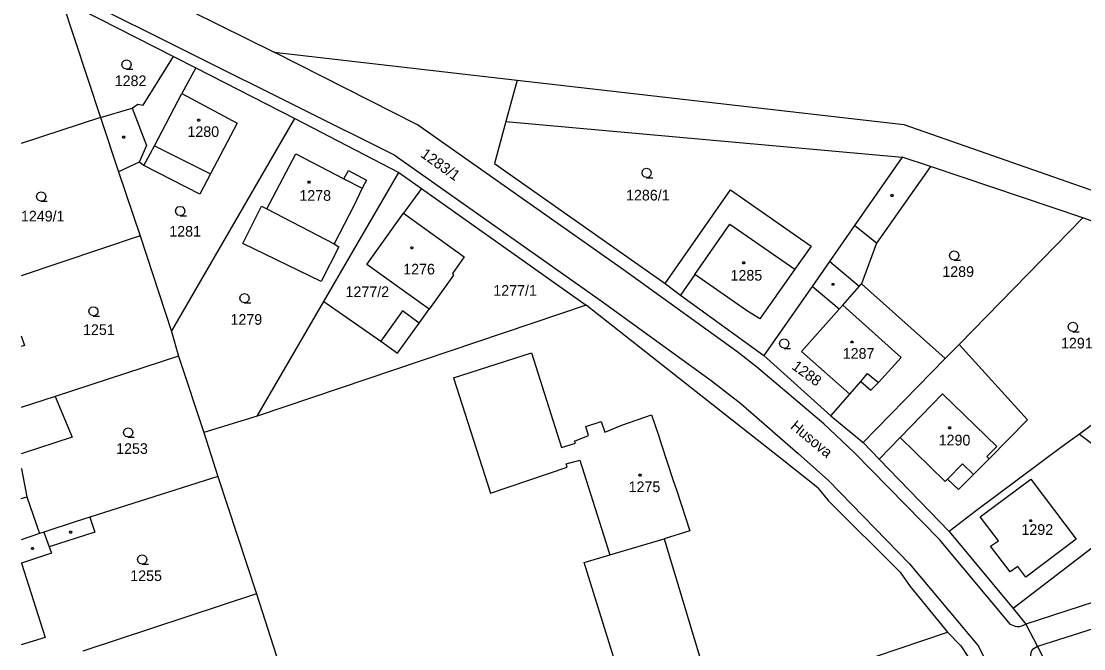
# Model space of a CAD drawing. Extents: x -621797 to -620972, y -1175539 to -1174697.
# Drawn here: x -621790.3 to -621620.7, y -1175230.7 to -1175130.5 of the extents above; entities that cross this region are included whole.
import ezdxf

# ---------------------------------------------------------------- set-up
doc = ezdxf.new("R2010")
doc.units = 0
for name, color, linetype in [('INZ mimo EON - nadz', 7, 'Continuous'), ('Rozvod plynu EON', 7, 'Continuous'), ('SDEL EON', 7, 'Continuous'), ('SDEL EON - popis', 7, 'Continuous'), ('Silnoproud EON', 7, 'Continuous'), ('Silnoproud EON - popis', 7, 'Continuous')]:
    doc.layers.add(name, color=color, linetype=linetype)

msp = doc.modelspace()

# ---------------------------------------------------------------- linework, layer by layer
at = {"layer": 'Rozvod plynu EON'}
for points in [[(-621761.88, -1175146.19), (-621761.79, -1175146.34), (-621761.88, -1175146.49), (-621762.06, -1175146.49), (-621762.15, -1175146.34), (-621762.06, -1175146.19)], [(-621773.89, -1175148.88), (-621773.8, -1175149.03), (-621773.89, -1175149.18), (-621774.07, -1175149.18), (-621774.16, -1175149.03), (-621774.07, -1175148.88)], [(-621744.28, -1175156.07), (-621744.19, -1175156.22), (-621744.28, -1175156.37), (-621744.46, -1175156.37), (-621744.55, -1175156.22), (-621744.46, -1175156.07)], [(-621651.23, -1175158.19), (-621651.14, -1175158.34), (-621651.23, -1175158.49), (-621651.41, -1175158.49), (-621651.5, -1175158.34), (-621651.41, -1175158.19)], [(-621727.87, -1175166.57), (-621727.78, -1175166.72), (-621727.87, -1175166.87), (-621728.05, -1175166.87), (-621728.14, -1175166.72), (-621728.05, -1175166.57)], [(-621674.89, -1175168.95), (-621674.8, -1175169.1), (-621674.89, -1175169.25), (-621675.07, -1175169.25), (-621675.16, -1175169.1), (-621675.07, -1175168.95)], [(-621660.62, -1175172.38), (-621660.53, -1175172.53), (-621660.62, -1175172.68), (-621660.8, -1175172.68), (-621660.89, -1175172.53), (-621660.8, -1175172.38)], [(-621657.59, -1175181.58), (-621657.5, -1175181.73), (-621657.59, -1175181.88), (-621657.77, -1175181.88), (-621657.86, -1175181.73), (-621657.77, -1175181.58)], [(-621642, -1175195.29), (-621641.91, -1175195.44), (-621642, -1175195.59), (-621642.18, -1175195.59), (-621642.27, -1175195.44), (-621642.18, -1175195.29)], [(-621691.46, -1175202.86), (-621691.37, -1175203.01), (-621691.46, -1175203.16), (-621691.64, -1175203.16), (-621691.73, -1175203.01), (-621691.64, -1175202.86)], [(-621629.07, -1175210.1), (-621628.98, -1175210.25), (-621629.07, -1175210.4), (-621629.25, -1175210.4), (-621629.34, -1175210.25), (-621629.25, -1175210.1)], [(-621782.35, -1175211.94), (-621782.26, -1175212.09), (-621782.35, -1175212.24), (-621782.53, -1175212.24), (-621782.62, -1175212.09), (-621782.53, -1175211.94)], [(-621788.42, -1175214.55), (-621788.33, -1175214.7), (-621788.42, -1175214.85), (-621788.6, -1175214.85), (-621788.69, -1175214.7), (-621788.6, -1175214.55)]]:
    msp.add_lwpolyline(points, close=True, dxfattribs=at)
at = {"layer": 'SDEL EON'}
for points in [[(-621773.48, -1175138.19), (-621773.86, -1175138.09), (-621774.13, -1175137.82), (-621774.23, -1175137.45), (-621774.13, -1175137.08), (-621773.86, -1175136.81), (-621773.49, -1175136.71), (-621773.12, -1175136.81), (-621772.85, -1175137.08), (-621772.75, -1175137.46), (-621772.85, -1175137.84), (-621773.12, -1175138.11), (-621773.5, -1175138.21), (-621772.5, -1175138.21)], [(-621690.46, -1175155.49), (-621690.84, -1175155.39), (-621691.11, -1175155.12), (-621691.21, -1175154.75), (-621691.11, -1175154.38), (-621690.84, -1175154.11), (-621690.47, -1175154.01), (-621690.1, -1175154.11), (-621689.83, -1175154.38), (-621689.73, -1175154.76), (-621689.83, -1175155.14), (-621690.1, -1175155.41), (-621690.48, -1175155.51), (-621689.48, -1175155.51)], [(-621787.14, -1175159.26), (-621787.52, -1175159.16), (-621787.79, -1175158.89), (-621787.89, -1175158.52), (-621787.79, -1175158.15), (-621787.52, -1175157.88), (-621787.15, -1175157.78), (-621786.78, -1175157.88), (-621786.51, -1175158.15), (-621786.41, -1175158.53), (-621786.51, -1175158.91), (-621786.78, -1175159.18), (-621787.16, -1175159.28), (-621786.16, -1175159.28)], [(-621764.93, -1175161.57), (-621765.31, -1175161.47), (-621765.58, -1175161.2), (-621765.68, -1175160.83), (-621765.58, -1175160.46), (-621765.31, -1175160.19), (-621764.94, -1175160.09), (-621764.57, -1175160.19), (-621764.3, -1175160.46), (-621764.2, -1175160.84), (-621764.3, -1175161.22), (-621764.57, -1175161.49), (-621764.95, -1175161.59), (-621763.95, -1175161.59)], [(-621641.36, -1175168.65), (-621641.74, -1175168.55), (-621642.01, -1175168.28), (-621642.11, -1175167.91), (-621642.01, -1175167.54), (-621641.74, -1175167.27), (-621641.37, -1175167.17), (-621641, -1175167.27), (-621640.73, -1175167.54), (-621640.63, -1175167.92), (-621640.73, -1175168.3), (-621641, -1175168.57), (-621641.38, -1175168.67), (-621640.38, -1175168.67)], [(-621754.66, -1175175.47), (-621755.04, -1175175.37), (-621755.31, -1175175.1), (-621755.41, -1175174.73), (-621755.31, -1175174.36), (-621755.04, -1175174.09), (-621754.67, -1175173.99), (-621754.3, -1175174.09), (-621754.03, -1175174.36), (-621753.93, -1175174.74), (-621754.03, -1175175.12), (-621754.3, -1175175.39), (-621754.68, -1175175.49), (-621753.68, -1175175.49)], [(-621778.79, -1175177.58), (-621779.17, -1175177.48), (-621779.44, -1175177.21), (-621779.54, -1175176.84), (-621779.44, -1175176.47), (-621779.17, -1175176.2), (-621778.8, -1175176.1), (-621778.43, -1175176.2), (-621778.16, -1175176.47), (-621778.06, -1175176.85), (-621778.16, -1175177.23), (-621778.43, -1175177.5), (-621778.81, -1175177.6), (-621777.81, -1175177.6)], [(-621622.41, -1175180.07), (-621622.79, -1175179.97), (-621623.06, -1175179.7), (-621623.16, -1175179.33), (-621623.06, -1175178.96), (-621622.79, -1175178.69), (-621622.42, -1175178.59), (-621622.05, -1175178.69), (-621621.78, -1175178.96), (-621621.68, -1175179.34), (-621621.78, -1175179.72), (-621622.05, -1175179.99), (-621622.43, -1175180.09), (-621621.43, -1175180.09)], [(-621668.5, -1175182.73), (-621668.88, -1175182.63), (-621669.15, -1175182.36), (-621669.25, -1175181.99), (-621669.15, -1175181.62), (-621668.88, -1175181.35), (-621668.51, -1175181.25), (-621668.14, -1175181.35), (-621667.87, -1175181.62), (-621667.77, -1175182), (-621667.87, -1175182.38), (-621668.14, -1175182.65), (-621668.52, -1175182.75), (-621667.52, -1175182.75)], [(-621773.25, -1175196.9), (-621773.63, -1175196.8), (-621773.9, -1175196.53), (-621774, -1175196.16), (-621773.9, -1175195.79), (-621773.63, -1175195.52), (-621773.26, -1175195.42), (-621772.89, -1175195.52), (-621772.62, -1175195.79), (-621772.52, -1175196.17), (-621772.62, -1175196.55), (-621772.89, -1175196.82), (-621773.27, -1175196.92), (-621772.27, -1175196.92)], [(-621771, -1175217.19), (-621771.38, -1175217.09), (-621771.65, -1175216.82), (-621771.75, -1175216.45), (-621771.65, -1175216.08), (-621771.38, -1175215.81), (-621771.01, -1175215.71), (-621770.64, -1175215.81), (-621770.37, -1175216.08), (-621770.27, -1175216.46), (-621770.37, -1175216.84), (-621770.64, -1175217.11), (-621771.02, -1175217.21), (-621770.02, -1175217.21)]]:
    msp.add_lwpolyline(points, dxfattribs=at)
at = {"layer": 'SDEL EON - popis'}
for p, q in [((-621783.22, -1175125.7), (-621745.71, -1175144.4)), ((-621727.07, -1175147.1), (-621749.91, -1175135.5)), ((-621769.06, -1175150.42), (-621764.69, -1175142.05)), ((-621772.58, -1175144.39), (-621770.3, -1175150.4)), ((-621745.71, -1175144.4), (-621730.8, -1175151.89)), ((-621694.18, -1175170.2), (-621727.07, -1175147.1)), ((-621770.3, -1175150.4), (-621771.49, -1175153.02)), ((-621770.72, -1175153.59), (-621769.06, -1175150.42)), ((-621769.06, -1175150.42), (-621760.1, -1175154.91)), ((-621730.8, -1175151.89), (-621697.74, -1175175.18)), ((-621738.82, -1175155.67), (-621735.86, -1175157.2)), ((-621751.1, -1175160.49), (-621740.33, -1175166.09)), ((-621682.8, -1175170.94), (-621677.18, -1175162.92)), ((-621677.18, -1175162.92), (-621666.81, -1175170.1)), ((-621653.77, -1175165.95), (-621657.29, -1175163.16)), ((-621656.54, -1175172.89), (-621661.29, -1175168.88)), ((-621676.09, -1175183.28), (-621694.18, -1175170.2)), ((-621659.16, -1175175.85), (-621656.54, -1175172.89)), ((-621656.54, -1175172.89), (-621656.18, -1175172.48)), ((-621697.74, -1175175.18), (-621680.17, -1175187.88)), ((-621659.73, -1175176.51), (-621659.16, -1175175.85)), ((-621649.83, -1175184.21), (-621659.16, -1175175.85)), ((-621729.46, -1175176.79), (-621732.9, -1175181.59)), ((-621726.78, -1175178.71), (-621729.46, -1175176.79)), ((-621672.93, -1175185.68), (-621676.09, -1175183.28)), ((-621721.33, -1175187.46), (-621708.86, -1175183.49)), ((-621708.86, -1175183.49), (-621704.06, -1175198.6)), ((-621653.46, -1175188.18), (-621649.83, -1175184.21)), ((-621662.16, -1175194.79), (-621672.93, -1175185.68)), ((-621721.33, -1175187.46), (-621715.42, -1175205.85)), ((-621680.17, -1175187.88), (-621675.41, -1175191.56)), ((-621658.05, -1175190.04), (-621656.29, -1175188.04)), ((-621656.29, -1175188.04), (-621655.19, -1175186.78)), ((-621656.29, -1175188.04), (-621654.66, -1175189.43)), ((-621655.19, -1175186.78), (-621653.46, -1175188.18)), ((-621654.66, -1175189.43), (-621653.46, -1175188.18)), ((-621643.22, -1175190), (-621650.01, -1175196.99)), ((-621634.59, -1175198.43), (-621643.22, -1175190)), ((-621675.41, -1175191.56), (-621666.27, -1175199.53)), ((-621694.41, -1175195.03), (-621689.67, -1175193.36)), ((-621689.67, -1175193.36), (-621688.6, -1175196.59)), ((-621700.19, -1175195.24), (-621697.71, -1175194.45)), ((-621697.71, -1175194.45), (-621697.15, -1175196.13)), ((-621697.15, -1175196.13), (-621694.41, -1175195.03)), ((-621657.34, -1175199.35), (-621662.16, -1175194.79)), ((-621701.98, -1175197.57), (-621699.73, -1175196.67)), ((-621699.73, -1175196.67), (-621700.19, -1175195.24)), ((-621688.6, -1175196.59), (-621688.13, -1175198.01)), ((-621704.06, -1175198.6), (-621701.85, -1175197.9)), ((-621701.85, -1175197.9), (-621701.98, -1175197.57)), ((-621688.13, -1175198.01), (-621686.21, -1175203.85)), ((-621636.17, -1175200), (-621634.59, -1175198.43)), ((-621666.27, -1175199.53), (-621661.43, -1175203.85)), ((-621643.73, -1175213.24), (-621657.34, -1175199.35)), ((-621635.81, -1175200.37), (-621636.17, -1175200)), ((-621715.42, -1175205.85), (-621703.14, -1175201.7)), ((-621703.31, -1175201.21), (-621701.12, -1175200.58)), ((-621703.14, -1175201.7), (-621703.31, -1175201.21)), ((-621701.12, -1175200.58), (-621696.98, -1175213.69)), ((-621642.44, -1175203.65), (-621640.04, -1175201.2)), ((-621640.04, -1175201.2), (-621638.28, -1175202.87)), ((-621790.31, -1175202.007), (-621790.29, -1175202)), ((-621637.21, -1175209.62), (-621629.13, -1175203.63)), ((-621629.13, -1175203.63), (-621621.89, -1175213.2)), ((-621686.21, -1175203.85), (-621685.72, -1175205.32)), ((-621685.72, -1175205.32), (-621683.56, -1175211.87)), ((-621661.43, -1175203.85), (-621648.53, -1175217.13)), ((-621790.31, -1175206.732), (-621789.44, -1175206.45)), ((-621634.32, -1175213.46), (-621637.21, -1175209.62)), ((-621786.69, -1175212.09), (-621785.86, -1175214.41)), ((-621683.56, -1175211.87), (-621687.68, -1175213.14)), ((-621696.98, -1175213.69), (-621696.54, -1175215.07)), ((-621696.34, -1175215.72), (-621687.68, -1175213.14)), ((-621687.68, -1175213.14), (-621681.17, -1175234.78)), ((-621632.38, -1175226.81), (-621643.73, -1175213.24)), ((-621635.56, -1175214.34), (-621634.32, -1175213.46)), ((-621621.89, -1175213.2), (-621629.95, -1175219.26)), ((-621696.54, -1175215.07), (-621696.34, -1175215.72)), ((-621632.44, -1175218.44), (-621635.56, -1175214.34)), ((-621790.31, -1175216.989), (-621790.29, -1175217.05)), ((-621700.46, -1175216.95), (-621696.34, -1175215.72)), ((-621693.77, -1175238.42), (-621700.46, -1175216.95)), ((-621648.53, -1175217.13), (-621637.47, -1175230.28)), ((-621631.22, -1175217.57), (-621632.44, -1175218.44)), ((-621629.95, -1175219.26), (-621631.22, -1175217.57)), ((-621637.47, -1175230.28), (-621625.14, -1175255.82))]:
    msp.add_line(p, q, dxfattribs=at)
for points in [[(-621629.91, -1175226.79), (-621631.34, -1175227.2), (-621632.38, -1175226.81)], [(-621628.06, -1175230.33), (-621629.04, -1175231.05), (-621629.18, -1175232.45)]]:
    msp.add_spline(points, degree=3, dxfattribs=at)
at = {"layer": 'Silnoproud EON'}
for p, q in [((-621774.82, -1175123.16), (-621749.91, -1175135.5)), ((-621783.91, -1175127), (-621777.64, -1175145.9)), ((-621783.91, -1175127), (-621766.01, -1175136.16)), ((-621749.91, -1175135.5), (-621711.12, -1175139.94)), ((-621770.84, -1175143.91), (-621766.01, -1175136.16)), ((-621766.01, -1175136.16), (-621762.45, -1175137.98)), ((-621762.45, -1175137.98), (-621764.69, -1175142.05)), ((-621762.45, -1175137.98), (-621746.62, -1175146.06)), ((-621711.12, -1175139.94), (-621712.93, -1175146.52)), ((-621711.12, -1175139.94), (-621649.41, -1175147.01)), ((-621764.69, -1175142.05), (-621755.84, -1175146.81)), ((-621772.58, -1175144.39), (-621771.71, -1175143.77)), ((-621771.71, -1175143.77), (-621770.84, -1175143.91)), ((-621777.64, -1175145.9), (-621790.31, -1175150.045)), ((-621777.64, -1175145.9), (-621772.58, -1175144.39)), ((-621777.64, -1175145.9), (-621774.76, -1175154.58)), ((-621766.31, -1175180.08), (-621746.62, -1175146.06)), ((-621755.84, -1175146.81), (-621760.1, -1175154.91)), ((-621746.62, -1175146.06), (-621730.05, -1175154.67)), ((-621712.93, -1175146.52), (-621714.78, -1175153.26)), ((-621712.93, -1175146.52), (-621649.66, -1175152.23)), ((-621649.41, -1175147.01), (-621602.94, -1175163.25)), ((-621751.1, -1175160.49), (-621746.47, -1175151.7)), ((-621746.47, -1175151.7), (-621738.82, -1175155.67)), ((-621649.66, -1175152.23), (-621657.29, -1175163.16)), ((-621645.15, -1175153.74), (-621649.66, -1175152.23)), ((-621771.49, -1175153.02), (-621774.76, -1175154.58)), ((-621770.72, -1175153.59), (-621771.49, -1175153.02)), ((-621761.79, -1175158.15), (-621770.72, -1175153.59)), ((-621738.82, -1175155.67), (-621738.08, -1175154.34)), ((-621738.08, -1175154.34), (-621735.18, -1175155.92)), ((-621714.78, -1175153.26), (-621687.53, -1175172.38)), ((-621645.15, -1175153.74), (-621653.77, -1175165.95)), ((-621620.81, -1175161.91), (-621645.15, -1175153.74)), ((-621774.76, -1175154.58), (-621771.35, -1175164.81)), ((-621760.1, -1175154.91), (-621761.79, -1175158.15)), ((-621742.02, -1175175.28), (-621730.05, -1175154.67)), ((-621735.18, -1175155.92), (-621735.86, -1175157.2)), ((-621730.05, -1175154.67), (-621726.42, -1175157.24)), ((-621735.86, -1175157.2), (-621737.14, -1175159.9)), ((-621726.42, -1175157.24), (-621729.27, -1175161.19)), ((-621726.42, -1175157.24), (-621700.14, -1175175.85)), ((-621687.53, -1175172.38), (-621677.09, -1175157.44)), ((-621677.09, -1175157.44), (-621664.22, -1175166.43)), ((-621754.96, -1175165.99), (-621751.98, -1175160.06)), ((-621751.98, -1175160.06), (-621751.1, -1175160.49)), ((-621737.14, -1175159.9), (-621740.33, -1175166.09)), ((-621735.16, -1175169.36), (-621729.27, -1175161.19)), ((-621729.27, -1175161.19), (-621719.61, -1175168.17)), ((-621620.81, -1175161.91), (-621640.6, -1175182.13)), ((-621606.85, -1175167.08), (-621620.81, -1175161.91)), ((-621657.29, -1175163.16), (-621661.29, -1175168.88)), ((-621771.35, -1175164.81), (-621790.31, -1175171.194)), ((-621771.35, -1175164.81), (-621766.31, -1175180.08)), ((-621742.44, -1175172.08), (-621754.96, -1175165.99)), ((-621740.33, -1175166.09), (-621739.59, -1175166.54)), ((-621653.77, -1175165.95), (-621656.18, -1175172.48)), ((-621739.59, -1175166.54), (-621742.44, -1175172.08)), ((-621664.22, -1175166.43), (-621666.81, -1175170.1)), ((-621725.2, -1175176.5), (-621735.16, -1175169.36)), ((-621719.61, -1175168.17), (-621721.48, -1175170.82)), ((-621661.29, -1175168.88), (-621664.05, -1175172.86)), ((-621721.32, -1175171.08), (-621725.2, -1175176.5)), ((-621721.48, -1175170.82), (-621721.32, -1175171.08)), ((-621682.8, -1175170.94), (-621685.07, -1175174.28)), ((-621674.51, -1175176.71), (-621682.8, -1175170.94)), ((-621666.81, -1175170.1), (-621672.42, -1175178.05)), ((-621687.53, -1175172.38), (-621685.07, -1175174.28)), ((-621664.05, -1175172.86), (-621671.77, -1175183.9)), ((-621659.73, -1175176.51), (-621664.05, -1175172.86)), ((-621656.18, -1175172.48), (-621642.8, -1175184.37)), ((-621685.07, -1175174.28), (-621671.77, -1175183.9)), ((-621752.64, -1175193.57), (-621742.02, -1175175.28)), ((-621700.14, -1175175.85), (-621752.64, -1175193.57)), ((-621742.02, -1175175.28), (-621732.9, -1175181.59)), ((-621726.78, -1175178.71), (-621725.2, -1175176.5)), ((-621680.81, -1175191.07), (-621700.14, -1175175.85)), ((-621665.77, -1175183.23), (-621659.73, -1175176.51)), ((-621593.5, -1175175.72), (-621621.38, -1175196.43)), ((-621672.42, -1175178.05), (-621674.51, -1175176.71)), ((-621730.22, -1175183.51), (-621726.78, -1175178.71)), ((-621790.31, -1175180.742), (-621789.79, -1175182.28)), ((-621766.31, -1175180.08), (-621765.22, -1175184.02)), ((-621732.9, -1175181.59), (-621730.22, -1175183.51)), ((-621789.79, -1175182.28), (-621790.31, -1175182.466)), ((-621658.05, -1175190.04), (-621665.77, -1175183.23)), ((-621640.6, -1175182.13), (-621642.8, -1175184.37)), ((-621640.6, -1175182.13), (-621629.65, -1175194.16)), ((-621765.22, -1175184.02), (-621784.87, -1175190.44)), ((-621765.22, -1175184.02), (-621761.16, -1175196.16)), ((-621671.77, -1175183.9), (-621661.08, -1175193.51)), ((-621642.8, -1175184.37), (-621655.93, -1175197.8)), ((-621661.08, -1175193.51), (-621658.05, -1175190.04)), ((-621784.87, -1175190.44), (-621790.31, -1175192.174)), ((-621784.87, -1175190.44), (-621782.19, -1175196.93)), ((-621668.85, -1175200.48), (-621680.81, -1175191.07)), ((-621661.08, -1175193.51), (-621655.93, -1175197.8)), ((-621752.64, -1175193.57), (-621761.16, -1175196.16)), ((-621629.65, -1175194.16), (-621635.81, -1175200.37)), ((-621761.16, -1175196.16), (-621758.93, -1175203.19)), ((-621621.38, -1175196.43), (-621624.17, -1175198.48)), ((-621621.38, -1175196.43), (-621602.09, -1175211.03)), ((-621782.19, -1175196.93), (-621790.31, -1175199.588)), ((-621655.93, -1175197.8), (-621653.36, -1175200.45)), ((-621650.01, -1175196.99), (-621653.36, -1175200.45)), ((-621642.81, -1175204.02), (-621650.01, -1175196.99)), ((-621624.17, -1175198.48), (-621638.02, -1175208.8)), ((-621790.31, -1175201.94), (-621790.29, -1175202)), ((-621663.13, -1175204.99), (-621668.85, -1175200.48)), ((-621653.36, -1175200.45), (-621642.18, -1175211.98)), ((-621635.81, -1175200.37), (-621638.28, -1175202.87)), ((-621790.29, -1175202), (-621789.44, -1175206.45)), ((-621758.93, -1175203.19), (-621779.36, -1175209.71)), ((-621758.93, -1175203.19), (-621752.76, -1175221.93)), ((-621642.44, -1175203.65), (-621642.81, -1175204.02)), ((-621640.68, -1175205.29), (-621642.44, -1175203.65)), ((-621638.28, -1175202.87), (-621640.68, -1175205.29)), ((-621663.13, -1175204.99), (-621661.47, -1175207.06)), ((-621789.44, -1175206.45), (-621787.37, -1175212.32)), ((-621661.47, -1175207.06), (-621650.02, -1175218.47)), ((-621781.7, -1175210.45), (-621786.69, -1175212.09)), ((-621779.36, -1175209.71), (-621781.7, -1175210.45)), ((-621779.36, -1175209.71), (-621778.56, -1175212.09)), ((-621638.02, -1175208.8), (-621642.18, -1175211.98)), ((-621786.69, -1175212.09), (-621787.37, -1175212.32)), ((-621778.56, -1175212.09), (-621785.86, -1175214.41)), ((-621642.18, -1175211.98), (-621631.96, -1175224.3)), ((-621787.37, -1175212.32), (-621790.31, -1175213.329)), ((-621618.03, -1175213.59), (-621631.96, -1175224.3)), ((-621785.5, -1175215.45), (-621790.29, -1175217.05)), ((-621785.86, -1175214.41), (-621785.5, -1175215.45)), ((-621790.29, -1175217.05), (-621786.5, -1175228.91)), ((-621650.02, -1175218.47), (-621648.42, -1175220.74)), ((-621610.03, -1175220.32), (-621629.91, -1175226.79)), ((-621752.76, -1175221.93), (-621780.5, -1175231.07)), ((-621752.76, -1175221.93), (-621746.4, -1175241.67)), ((-621648.42, -1175220.74), (-621642.42, -1175228.04)), ((-621607.52, -1175223.78), (-621628.06, -1175230.33)), ((-621631.96, -1175224.3), (-621629.91, -1175226.79)), ((-621629.91, -1175226.79), (-621628.06, -1175230.33)), ((-621786.5, -1175228.91), (-621790.31, -1175230.067)), ((-621693.85, -1175245.36), (-621642.42, -1175228.04)), ((-621642.42, -1175228.04), (-621640.31, -1175230.23)), ((-621640.31, -1175230.23), (-621639.21, -1175231.96)), ((-621628.06, -1175230.33), (-621618.87, -1175248.42))]:
    msp.add_line(p, q, dxfattribs=at)

# ---------------------------------------------------------------- texts
at = {"layer": 'INZ mimo EON - nadz'}
msp.add_text('Husova', height=1.7, rotation=320.398, dxfattribs=at).set_placement((-621667.635, -1175195.418))
at = {"layer": 'Silnoproud EON - popis'}
for s, p in [('1282', (-621775.387, -1175140.89)), ('1280', (-621763.777, -1175149.01)), ('1278', (-621745.909, -1175159.2)), ('1286/1', (-621693.757, -1175159.15)), ('1249/1', (-621790.36, -1175162.5)), ('1281', (-621766.677, -1175164.92)), ('1276', (-621729.329, -1175170.96)), ('1289', (-621643.267, -1175171.35)), ('1285', (-621677.077, -1175171.94)), ('1277/2', (-621738.537, -1175174.57)), ('1277/1', (-621714.947, -1175174.36)), ('1279', (-621756.907, -1175178.99)), ('1251', (-621780.447, -1175180.62)), ('1291', (-621624.317, -1175182.77)), ('1287', (-621659.167, -1175184.41)), ('1290', (-621643.847, -1175198.25)), ('1253', (-621775.157, -1175199.6)), ('1275', (-621693.347, -1175205.7)), ('1292', (-621630.637, -1175212.52)), ('1255', (-621772.907, -1175219.89))]:
    msp.add_text(s, height=1.7, dxfattribs=at).set_placement(p)
for s, rotation, p in [('1283/1', 324.466, (-621726.691, -1175152.08)), ('1288', 324.00763, (-621667.432, -1175185.931))]:
    msp.add_text(s, height=1.7, rotation=rotation, dxfattribs=at).set_placement(p)

doc.saveas('drawing.dxf')
